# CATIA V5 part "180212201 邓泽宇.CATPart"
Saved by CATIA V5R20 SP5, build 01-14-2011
Part number: zuoye
Bounding box of the stored display mesh (mm): x -39.1 to 39.1, y -78.75 to 78.75, z -2.3 to 7.7
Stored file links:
  E:\dzy\zuoye4.19.CATPart
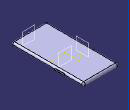
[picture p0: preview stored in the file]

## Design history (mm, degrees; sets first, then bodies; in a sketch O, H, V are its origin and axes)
Body1 (main body)
  Sketch1 on xy-plane, origin (0, 0, 0), H (1, 0, 0), V (0, 1, 0)
    line L1 (38.7, 78.75) -> (38.7, -78.75)
    line L2 (38.7, -78.75) -> (-38.7, -78.75)
    line L3 (-38.7, -78.75) -> (-38.7, 78.75)
    line L4 (-38.7, 78.75) -> (38.7, 78.75)
    length L4 = 77.4
    length L1 = 157.5
    vertical: L1 V, L3 V
    horizontal: L2 H, L4 H
    equidistance: L1 L3 O, L2 L4 O
  Pad1: profile Sketch1, direction (0, 0, 1), length 7.7
  Fillet1: radius 3.85, on face of Pad1 from Sketch1.L1; end face of Pad1; face of Pad1 from Sketch1.L3; start face of Pad1
  Sketch2 on xy-plane, origin (0, 0, 0), H (1, 0, 0), V (0, 1, 0)
    construction line L1 (25, 65) -> (25, 45)
    point P2 (25, 45)
    line L2 (30.5, 65) -> (30.5, 45)
    line L3 (19.5, 45) -> (19.5, 65)
    arc A1 centre (25, 45) radius 5.5 from (30.5, 45) to (19.5, 45) cw
    arc A2 centre (25, 65) radius 5.5 from (19.5, 65) to (30.5, 65) cw
    distance L1 L2 = 5.5
    length L1 = 20
    distance P2 H = 45
    distance V P2 = 25
    vertical: L1 V
    tangency: A1 L2, A2 L2, A1 L3, A2 L3
  Pad2: profile Sketch2, direction (0, 0, -1), length 2
  Sketch3 on yz-plane, origin (0, 0, 0), H (0, 1, 0), V (0, 0, 1)
    construction line L1 (20, 4) -> (38, 4)
    point P1 (20, 4)
    line L2 (20, 5) -> (38, 5)
    line L3 (38, 3) -> (20, 3)
    arc A1 centre (38, 4) radius 1 from (38, 5) to (38, 3) cw
    arc A2 centre (20, 4) radius 1 from (20, 3) to (20, 5) cw
    distance L1 L2 = 1
    distance P1 V = 20
    length L3 = 18
    distance P1 H = 4
    horizontal: L1 H
    tangency: A1 L2, A2 L2, A1 L3, A2 L3
  Pad3: profile Sketch3, direction (1, 0, 0), length 38.5
  Plane1: type Offset, RefPlane yz-plane, Offset 37.2
  Sketch4 on Plane1, origin (37.2, 0, 0), H (0, 1, 0), V (0, 0, 1)
    construction line L1 (18, 4) -> (37, 4)
    point P1 (18, 4)
    line L2 (18, 5.5) -> (37, 5.5)
    line L3 (37, 2.5) -> (18, 2.5)
    arc A1 centre (37, 4) radius 1.5 from (37, 5.5) to (37, 2.5) cw
    arc A2 centre (18, 4) radius 1.5 from (18, 2.5) to (18, 5.5) cw
    distance L1 L2 = 1.5
    length L2 = 19
    distance H L3 = 2.5
    distance P1 V = 18
    horizontal: L1 H
    tangency: A1 L2, A2 L2, A1 L3, A2 L3
  Pad4: profile Sketch4, direction (1, 0, 0), length 1.9
  Sketch5 on end face of Pad2, origin (0, 0, -2), H (1, 0, 0), V (0, -1, 0)
    axis line L1 (25.5804, -29.4018) -> (25.5804, -76.8354)
    circle A1 centre (25.5804, -47.2721) radius 3
    point P3 (25.5804, -47.2721)
    circle A2 centre (25.5804, -55.4351) radius 2.5
    point P4 (25.5804, -55.4351)
    circle A3 centre (25.5804, -63.8187) radius 3
    point P5 (25.5804, -63.8187)
    radius A1 = 3
    radius A2 = 2.5
    radius A3 = 3
    vertical: L1 V
    coincidence: P3 L1, P4 L1, P5 L1
  Pad5: profile Sketch5, direction (0, 0, -1), length 0.1
  Pocket1: profile end face of Pad5, direction along end face of Pad2 reversed, length 0.2
  Pad6: profile end face of Pad5, direction along end face of Pad2, length 0.2
  Pad7: profile end face of Pad5, direction along end face of Pad2, length 0.2
  Sketch6 on end face of Pad1, origin (0, 0, 7.7), H (1, 0, 0), V (0, 1, 0)
    axis line L1 (50, 30) -> (-90, 30)
    horizontal: L1 H
  Plane2: type Offset, RefPlane yz-plane, Offset 37.2, reversed
  Plane3: type Offset, RefPlane yz-plane, Offset 37.2, reversed
  Sketch7 on Plane3, origin (-37.2, 0, 0), H (0, 1, 0), V (0, 0, 1)
    construction line L1 (10, 3.87) -> (16, 3.87)
    point P1 (10, 3.87)
    line L2 (10, 4.87) -> (16, 4.87)
    line L3 (16, 2.87) -> (10, 2.87)
    arc A1 centre (16, 3.87) radius 1 from (16, 4.87) to (16, 2.87) cw
    arc A2 centre (10, 3.87) radius 1 from (10, 2.87) to (10, 4.87) cw
    reference projected line E1 (-74.9, 3.85) -> (74.9, 3.85) from edge [face of Fillet1 | face of Fillet1]
    construction line L4 (20, 3.89) -> (26, 3.89)
    point P7 (20, 3.89)
    line L5 (20, 4.89) -> (26, 4.89)
    line L6 (26, 2.89) -> (20, 2.89)
    arc A3 centre (26, 3.89) radius 1 from (26, 4.89) to (26, 2.89) cw
    arc A4 centre (20, 3.89) radius 1 from (20, 2.89) to (20, 4.89) cw
    distance L1 L2 = 1
    length L1 = 6
    distance P1 V = 10
    distance L1 E1 = 0.02
    distance L4 L5 = 1
    length L4 = 6
    distance L4 L1 = 0.02
    distance P7 V = 20
    horizontal: L1 H, L4 H
    tangency: A1 L2, A2 L2, A1 L3, A2 L3, A3 L5, A4 L5, A3 L6, A4 L6
  Pad8: profile Sketch7, direction (-1, 0, 0), length 1.9
  Plane4: type Offset, RefPlane zx-plane, Offset 78.75, reversed
  Sketch8 on Plane4, origin (0, -78.75, 0), H (-1, 0, 0), V (0, 0, 1)
    construction line L1 (4, 4) -> (-4, 4)
    point P1 (4, 4)
    line L2 (4, 3) -> (-4, 3)
    line L3 (-4, 5) -> (4, 5)
    arc A1 centre (-4, 4) radius 1 from (-4, 3) to (-4, 5) cw
    arc A2 centre (4, 4) radius 1 from (4, 5) to (4, 3) cw
    distance L1 L2 = 1
    length L1 = 8
    distance V P1 = 4
    distance H L1 = 4
    horizontal: L1 H
    tangency: A1 L2, A2 L2, A1 L3, A2 L3
  Pocket2: profile Sketch8, direction (0, 1, 0), length 10
  Sketch9 on Plane4, origin (0, -78.75, 0), H (-1, 0, 0), V (0, 0, 1)
    circle A1 centre (10, 4) radius 0.5
    point P1 (10, 4)
    circle A2 centre (11.5, 4) radius 0.5
    point P2 (11.5, 4)
    circle A3 centre (13, 4) radius 0.5
    point P3 (13, 4)
    circle A4 centre (14.5, 4) radius 0.5
    point P4 (14.5, 4)
    circle A5 centre (8.5, 4) radius 0.5
    point P5 (8.5, 4)
    circle A6 centre (-8.5, 4) radius 0.5
    point P6 (-8.5, 4)
    circle A7 centre (-10, 4) radius 0.5
    point P7 (-10, 4)
    circle A8 centre (-11.5, 4) radius 0.5
    point P8 (-11.5, 4)
    circle A9 centre (-13, 4) radius 0.5
    point P9 (-13, 4)
    circle A10 centre (-14.5, 4) radius 0.5
    point P10 (-14.5, 4)
    polyline C1
    polyline C2
    polyline C3
    polyline C4
    polyline C5
    polyline C6
    polyline C7
    polyline C8
    polyline C9
    polyline C10
    polyline C11
    polyline C12
    polyline C13
    polyline C14
    polyline C15
    polyline C16
    polyline C17
    polyline C18
    polyline C19
    polyline C20
    polyline C21
    polyline C22
    polyline C23
    polyline C24
    polyline C25
    polyline C26
    polyline C27
    polyline C28
    polyline C29
    polyline C30
    polyline C31
    polyline C32
    polyline C33
    polyline C34
    polyline C35
    polyline C36
    polyline C37
    polyline C38
    polyline C39
    polyline C40
    polyline C41
    polyline C42
    polyline C43
    polyline C44
    polyline C45
    polyline C46
    polyline C47
    polyline C48
    radius A1 = 0.5
    distance P1 H = 4
    distance P1 V = 10
    radius A2 = 0.5
    distance P2 H = 4
    distance P2 V = 11.5
    radius A3 = 0.5
    distance P3 H = 4
    distance P3 V = 13
    radius A4 = 0.5
    distance P4 H = 4
    distance P4 V = 14.5
    radius A5 = 0.5
    distance P5 V = 8.5
    distance P5 H = 4
    radius A6 = 0.5
    distance P6 V = 8.5
    distance P6 H = 4
    radius A7 = 0.5
    distance P7 V = 10
    distance P7 H = 4
    radius A8 = 0.5
    distance P8 V = 11.5
    distance P8 H = 4
    radius A9 = 0.5
    distance P9 V = 13
    distance P9 H = 4
    radius A10 = 0.5
    distance P10 V = 14.5
    distance P10 H = 4
  Pocket3: profile Sketch9, direction (0, 1, 0), length 5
